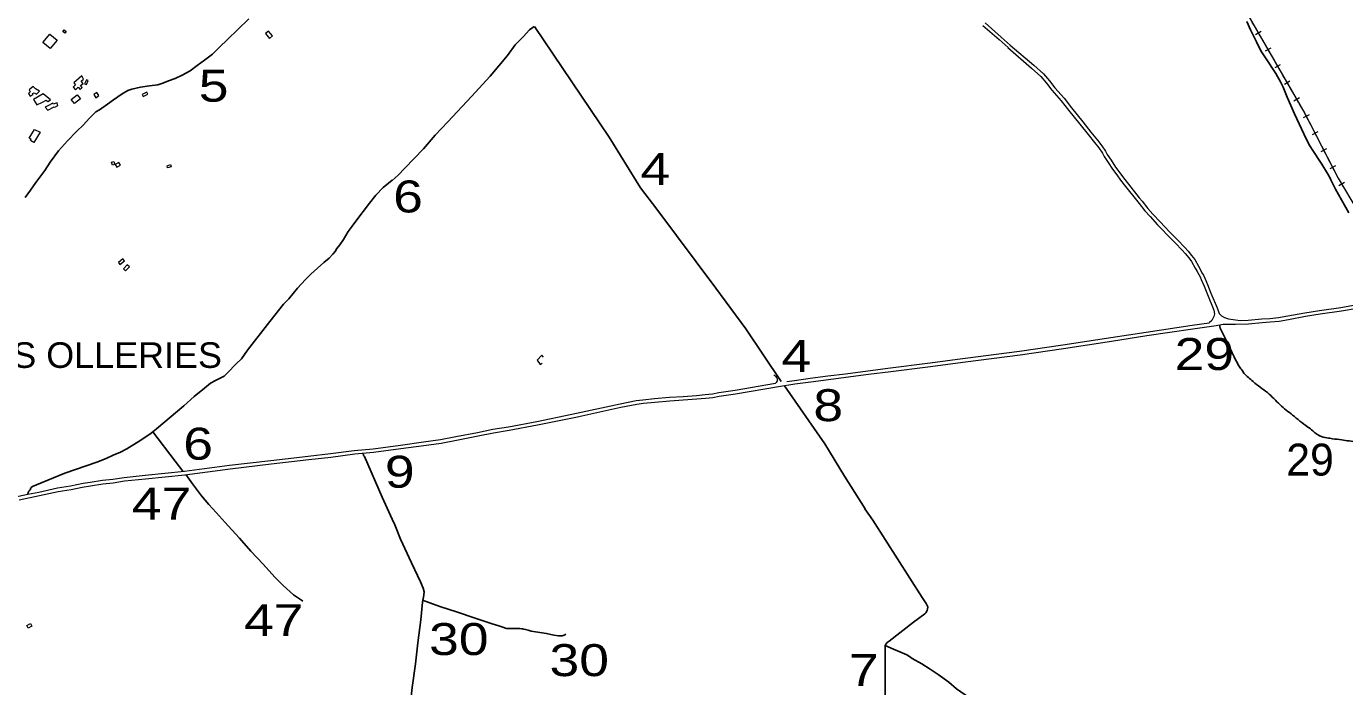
# Model space of a CAD drawing. Extents: x 476989 to 498418, y 4381813 to 4416555.
# Drawn here: x 485599 to 487660, y 4384627 to 4385659 of the extents above; entities that cross this region are included whole.
import ezdxf
from ezdxf.enums import TextEntityAlignment as Align

# ---------------------------------------------------------------- set-up
doc = ezdxf.new("R2010")
doc.units = 0
doc.header["$LTSCALE"] = 20
doc.linetypes.add('MEDIUM_DASHED', pattern=[4.5, 3, -1.5])
for name, color, linetype, lineweight in [('13', 7, 'Continuous', 13), ('34', 7, 'Continuous', 13), ('36', 7, 'Continuous', 13), ('47', 7, 'Continuous', 13), ('48', 7, 'MEDIUM_DASHED', 13), ('6', 7, 'Continuous', 25)]:
    doc.layers.add(name, color=color, linetype=linetype, lineweight=lineweight)
doc.layers.add('7', color=7, linetype='Continuous')

msp = doc.modelspace()

# ---------------------------------------------------------------- linework, layer by layer
at = {"layer": '34'}
for p, q in [((487515.47, 4385665.98), (487520.47, 4385657.32)), ((487529.79, 4385651.17), (487521.13, 4385646.17)), ((487522.96, 4385653), (487527.96, 4385644.34)), ((487530.46, 4385640.01), (487535.46, 4385631.35)), ((487537.96, 4385627.03), (487542.96, 4385618.36)), ((487544.79, 4385625.19), (487536.13, 4385620.2)), ((487545.45, 4385614.03), (487550.45, 4385605.37)), ((487559.78, 4385599.22), (487551.12, 4385594.22)), ((487552.95, 4385601.05), (487557.95, 4385592.39)), ((487560.45, 4385588.06), (487565.45, 4385579.4)), ((487574.77, 4385573.25), (487566.11, 4385568.25)), ((487567.94, 4385575.08), (487572.94, 4385566.42)), ((487575.44, 4385562.09), (487580.44, 4385553.43)), ((487589.76, 4385547.27), (487581.1, 4385542.27)), ((487582.93, 4385549.1), (487587.93, 4385540.44)), ((487590.43, 4385536.11), (487595.43, 4385527.45)), ((487604.67, 4385520.98), (487595.77, 4385516.4)), ((487604.8, 4385509.8), (487609.37, 4385500.91)), ((487618.39, 4385494.31), (487609.5, 4385489.74)), ((487611.66, 4385496.47), (487616.24, 4385487.58)), ((487618.53, 4385483.13), (487623.1, 4385474.24)), ((487632.12, 4385467.65), (487623.23, 4385463.07)), ((487625.39, 4385469.81), (487629.96, 4385460.92)), ((487632.25, 4385456.47), (487636.83, 4385447.58)), ((487639.11, 4385443.14), (487643.69, 4385434.25)), ((487645.85, 4385440.99), (487636.96, 4385436.41)), ((487660.04, 4385414.94), (487651.46, 4385409.81)), ((487653.19, 4385416.67), (487658.31, 4385408.09))]:
    msp.add_line(p, q, dxfattribs=at)
for points in [[(487280.6, 4386441.97), (487080, 4386339), (487267, 4386051), (487354, 4385933), (487441, 4385795), (487598, 4385523), (487650, 4385422), (487680.1, 4385371.64)], [(487597.92, 4385523.13), (487598, 4385523), (487602.51, 4385514.24)], [(487645.98, 4385429.81), (487650, 4385422), (487650.63, 4385420.95)]]:
    msp.add_lwpolyline(points, dxfattribs=at)
at = {"layer": '36'}
for points in [[(487094.87, 4385660.71), (487120.03, 4385638.46), (487134.03, 4385626.1)], [(487098.08, 4385664.55), (487123.34, 4385642.2), (487137.34, 4385629.84)], [(487137.34, 4385629.84), (487174.37, 4385598.25), (487189.49, 4385584.88), (487198.79, 4385573.94), (487207.09, 4385563.07), (487221.62, 4385546.65), (487233.12, 4385531.62), (487250.93, 4385509.8), (487263.67, 4385493.87), (487273.88, 4385481.46), (487280.75, 4385472.58), (487286.58, 4385464.01), (487289.2, 4385458.89), (487295.51, 4385449.72), (487302.21, 4385439.2), (487308.8, 4385430.25), (487314.57, 4385422.26), (487322.22, 4385412.29), (487339.33, 4385391.04), (487343.7, 4385385.7), (487352.58, 4385374.47), (487360.7, 4385365.72), (487372.3, 4385352.95), (487378.61, 4385346.17), (487387.71, 4385336.64), (487399.47, 4385324.69), (487410.47, 4385313.22), (487415.59, 4385307.71), (487421.16, 4385300.88), (487426.05, 4385294.47), (487431.8, 4385284.22), (487435.11, 4385278.47), (487437.31, 4385273.99), (487439.69, 4385270.26), (487441.61, 4385265.57), (487446.06, 4385255.26), (487451.29, 4385241.96), (487461.05, 4385218.86)], [(487133.89, 4385626.23), (487170.51, 4385593.8), (487185.28, 4385580.75), (487194.21, 4385570.25), (487202.54, 4385559.33), (487217.08, 4385542.91), (487228.5, 4385527.97), (487246.35, 4385506.1), (487259.1, 4385490.16), (487269.28, 4385477.79), (487275.98, 4385469.12), (487281.5, 4385461), (487284.13, 4385455.86), (487290.6, 4385446.47), (487297.35, 4385435.87), (487304.04, 4385426.78), (487309.85, 4385418.74), (487317.59, 4385408.66), (487334.76, 4385387.33), (487339.11, 4385382.01), (487348.1, 4385370.63), (487356.37, 4385361.74), (487367.97, 4385348.97), (487374.33, 4385342.13), (487383.49, 4385332.54), (487395.25, 4385320.59), (487406.19, 4385309.18), (487411.15, 4385303.84), (487416.54, 4385297.24), (487421.12, 4385291.23), (487426.69, 4385281.31), (487429.91, 4385275.71), (487432.17, 4385271.1), (487434.44, 4385267.53), (487436.19, 4385263.29), (487440.62, 4385253.02), (487445.84, 4385239.74), (487455.81, 4385215.58)], [(485587.94, 4384918.87), (485619.65, 4384925.47), (485648.99, 4384932.03), (485669.04, 4384935.03), (485686.15, 4384938.36), (485699.65, 4384940.84), (485718.69, 4384943.79), (485734.94, 4384945.58), (485752.53, 4384948.26), (485785.29, 4384951.54), (485846.98, 4384958.08), (485917.59, 4384967.28), (485981.92, 4384974.91), (486040.54, 4384981.65), (486075.35, 4384985.5), (486112.55, 4384990.45), (486141.85, 4384993.18), (486184.72, 4384998.94), (486220.81, 4385003.83), (486247.67, 4385007.48), (486271.61, 4385012.25), (486305.54, 4385018.75), (486329.76, 4385023.58), (486353.89, 4385027.57), (486398.31, 4385035.88), (486461.13, 4385048.69), (486462.73, 4385049.14), (486528.81, 4385063.65), (486553.7, 4385068.46), (486563.83, 4385069.82), (486581.63, 4385071.52), (486605.36, 4385073.58), (486626.31, 4385074.93), (486647.28, 4385076.51), (486661.18, 4385077.81), (486672.55, 4385078.92), (486682.57, 4385080.87), (486708.05, 4385084.63), (486775.37, 4385096.2), (486800.8, 4385100.04), (486825.52, 4385103.44), (486853.12, 4385107.17), (486880.63, 4385110.38), (486915.74, 4385115.13), (486950.76, 4385119.43), (487008.87, 4385126.93), (487067.66, 4385134.49), (487152.91, 4385145.5), (487220.82, 4385155.63), (487295.65, 4385167.08), (487350.85, 4385175.59), (487422.95, 4385186.43), (487459.43, 4385191.37), (487470.68, 4385193.32), (487489.65, 4385193.71), (487510.01, 4385193.94), (487531.2, 4385196.06), (487543.67, 4385196.93), (487557.74, 4385198.3), (487572.8, 4385201.01), (487598.91, 4385205.81), (487622.06, 4385209.39), (487655.21, 4385214.16), (487679.8, 4385218.38)], [(487455.81, 4385215.58), (487456.62, 4385209.72), (487455.81, 4385205.68), (487454.49, 4385202.09), (487452.5, 4385199.34), (487448.32, 4385195.53)], [(487461.05, 4385218.86), (487463.98, 4385210.29), (487467.68, 4385206.41), (487472.37, 4385203.71), (487478.72, 4385201.9), (487497.15, 4385199.42)], [(487497.15, 4385199.42), (487509.69, 4385199.56), (487530.73, 4385201.64), (487543.2, 4385202.51), (487556.97, 4385203.85), (487571.79, 4385206.52), (487597.97, 4385211.35), (487621.23, 4385214.93), (487654.34, 4385219.7), (487679.81, 4385224.07)], [(486788.13, 4385103.8), (486799.99, 4385105.59), (486824.76, 4385108.99), (486852.42, 4385112.73), (486879.93, 4385115.94), (486915.02, 4385120.69), (486950.06, 4385124.99), (487008.15, 4385132.49), (487066.94, 4385140.05), (487152.14, 4385151.05), (487219.98, 4385161.17), (487294.79, 4385172.63), (487350, 4385181.14), (487422.16, 4385191.98), (487448.32, 4385195.53)], [(485601.44, 4384927.38), (485618.46, 4384930.95), (485647.97, 4384937.54), (485668, 4384940.55), (485688.12, 4384944.59), (485698.86, 4384946.38), (485717.96, 4384949.34), (485734.21, 4384951.14), (485751.82, 4384953.82), (485784.71, 4384957.11), (485846.33, 4384963.64), (485916.89, 4384972.84), (485981.27, 4384980.47), (486039.91, 4384987.22), (486074.67, 4384991.06), (486111.92, 4384996.02), (486141.22, 4384998.75), (486183.97, 4385004.49), (486220.05, 4385009.38), (486246.73, 4385013.02), (486270.53, 4385017.75), (486304.46, 4385024.25), (486328.75, 4385029.09), (486352.92, 4385033.1), (486397.22, 4385041.38), (486452.17, 4385052.61), (486452.19, 4385052.58), (486527.68, 4385069.14), (486552.8, 4385074), (486563.2, 4385075.39), (486581.12, 4385077.1), (486604.95, 4385079.16), (486625.92, 4385080.52), (486646.81, 4385082.09), (486660.65, 4385083.38), (486671.74, 4385084.47), (486681.62, 4385086.4), (486707.17, 4385090.17), (486770.61, 4385101.07)], [(485422.69, 4384896.4), (485445.04, 4384898.28), (485457.06, 4384899.22), (485464.89, 4384900.34), (485474.69, 4384902.21), (485508.34, 4384907.79), (485538.44, 4384915.04), (485558.81, 4384919.82), (485586.93, 4384924.38), (485601.44, 4384927.38)]]:
    msp.add_lwpolyline(points, dxfattribs=at)
msp.add_spline([(486767.68, 4385114.39), (486772.5, 4385109.36), (486772.99, 4385106.58), (486772.97, 4385105.38), (486772.81, 4385104.41), (486772.42, 4385103.66), (486770.74, 4385101.28), (486770.61, 4385101.07)], degree=3, dxfattribs=at)
at = {"layer": '47'}
for points in [[(485635.68, 4385647.23), (485647.33, 4385637.86), (485636.56, 4385624.48), (485624.91, 4385633.85)], [(485658.29, 4385653.66), (485661.38, 4385650.92), (485659.34, 4385648.62), (485656.25, 4385651.36)], [(485973.2, 4385647.8), (485979.51, 4385640.27), (485984.18, 4385644.19), (485977.87, 4385651.72)], [(485619.69, 4385557.64), (485613.67, 4385561.55), (485609.59, 4385565.06), (485603.44, 4385559.82), (485605.27, 4385556.65), (485602.46, 4385554.21), (485604.95, 4385550.05), (485609.94, 4385552.83), (485608.92, 4385554.42), (485611.48, 4385555.06), (485615.13, 4385553.2)], [(485686, 4385582.05), (485673.31, 4385570.9), (485676.11, 4385567.69), (485672.26, 4385564.34), (485675.87, 4385560.17), (485680.34, 4385564.05), (485683.31, 4385560.61), (485686.6, 4385563.46), (485683.93, 4385566.52), (485687.71, 4385569.83), (485684.68, 4385573.28), (485688.41, 4385576.56)], [(485693.04, 4385575.65), (485690.28, 4385569.34), (485693, 4385568.15), (485695.76, 4385574.46)], [(485625.19, 4385553.51), (485610.05, 4385544.72), (485615.41, 4385536.24), (485624.62, 4385540.46), (485630.23, 4385543.98), (485632.89, 4385541.54), (485636.84, 4385544.49)], [(485683.68, 4385545.62), (485674.4, 4385538.3), (485669.11, 4385545), (485678.39, 4385552.32)], [(485709.41, 4385555.83), (485704.45, 4385552.39), (485707.72, 4385547.67), (485712.68, 4385551.11)], [(485787.53, 4385556.14), (485780.27, 4385552.57), (485781.8, 4385549.46), (485789.06, 4385553.03)], [(485647.5, 4385539.76), (485641.24, 4385537.45), (485640.36, 4385539.11), (485632.5, 4385534.95), (485628.57, 4385532.83), (485632.55, 4385528.34), (485642.83, 4385533.52), (485643.57, 4385532.76), (485648.26, 4385535.32)], [(485620.73, 4385493.69), (485610.59, 4385477.56), (485605.81, 4385480.55), (485606.79, 4385482.13), (485603.55, 4385484.13), (485612.08, 4385497.96)], [(485736, 4385447.7), (485737.37, 4385443.37), (485733.82, 4385442.25), (485732.45, 4385446.58)], [(485743.71, 4385446.46), (485738.03, 4385443.02), (485740.6, 4385438.78), (485746.28, 4385442.22)], [(485819.05, 4385441.33), (485824.55, 4385443.01), (485825.55, 4385439.73), (485820.05, 4385438.05)], [(485750.18, 4385295.54), (485742.99, 4385289.76), (485745.4, 4385286.76), (485752.59, 4385292.54)], [(485756.95, 4385286.22), (485750.76, 4385280.13), (485753.96, 4385276.88), (485760.15, 4385282.97)]]:
    msp.add_lwpolyline(points, close=True, dxfattribs=at)
at = {"layer": '48'}
msp.add_lwpolyline([(486407.83, 4385141.71), (486405.11, 4385144.87), (486397.87, 4385137.02), (486402.73, 4385130.49), (486405.67, 4385132.69)], dxfattribs=at)
msp.add_lwpolyline([(485599.77, 4384722.32), (485605.45, 4384725.41), (485607.85, 4384721), (485602.17, 4384717.91)], close=True, dxfattribs=at)
at = {"layer": '6'}
msp.add_line((486218.81, 4384761.9), (486218.38, 4384758.97), dxfattribs=at)
for points in [[(485597.52, 4385391.7), (485605.43, 4385403.19), (485614.06, 4385415.16), (485627.96, 4385433.84), (485636.16, 4385446.72), (485649.17, 4385464.38), (485663.28, 4385479.94), (485677.54, 4385494.69), (485688.56, 4385504.94), (485697.1, 4385515.25), (485707.8, 4385525.57), (485713.5, 4385528.66), (485725.91, 4385537.47), (485735.62, 4385544.46), (485748.75, 4385553.59), (485758, 4385558.72), (485764.17, 4385561.06), (485777.52, 4385563.88), (485791.81, 4385566), (485804.8, 4385567.91), (485812.68, 4385570.49), (485821.36, 4385573.88), (485831.97, 4385577.48), (485842.83, 4385582.78), (485855.2, 4385589.43), (485865.96, 4385597.89), (485877.72, 4385606.2), (485890.29, 4385615.9), (485901.17, 4385626.54), (485913.87, 4385638.89), (485929.7, 4385654.12), (485947.21, 4385671)], [(486171.07, 4385418.2), (486180.45, 4385426.71), (486190.85, 4385437.61), (486220.01, 4385467.74), (486238.45, 4385489.11), (486258.12, 4385510.06), (486294.91, 4385549.3), (486324.2, 4385581.38), (486338.08, 4385597.54), (486351.44, 4385613.56), (486363.48, 4385630.43), (486375.73, 4385642.67), (486386.01, 4385653.7), (486393.28, 4385659.16)], [(486779.18, 4385103.59), (486724.1, 4385186.32), (486677.34, 4385249.63), (486584.76, 4385373.47), (486559.43, 4385406.45), (486510.37, 4385486.01), (486393.48, 4385659.09)], [(487666.97, 4385367.8), (487655.53, 4385387.66), (487646.04, 4385404.85), (487638.87, 4385419.17), (487637.07, 4385422.61), (487633.76, 4385428.95), (487624.95, 4385443.57), (487619.44, 4385451.28), (487613.84, 4385460.27), (487610.6, 4385465.19), (487606.19, 4385472.22), (487600.82, 4385482.25), (487593.07, 4385498.8), (487581.97, 4385522.18), (487570.38, 4385548.55), (487564.1, 4385563.94), (487559.97, 4385572.22), (487552.83, 4385585.27), (487536.84, 4385609.75), (487529.21, 4385621.16), (487522.63, 4385634.9), (487513.12, 4385653.9), (487507.22, 4385666.93)], [(485802.83, 4385029.77), (485845.6, 4385065.72), (485861.7, 4385080.31), (485877.49, 4385093.53), (485887.3, 4385101.32), (485895.1, 4385105.6), (485908.18, 4385112.39), (485917.95, 4385121.44), (485922.84, 4385127.37), (485927.25, 4385131.59), (485935.63, 4385139.13), (485945.14, 4385152.95), (485979.77, 4385197.7), (486001.38, 4385224.55), (486009.54, 4385233.3), (486023.28, 4385249.97), (486035.47, 4385263.38), (486043.92, 4385271.58), (486054.18, 4385280.81), (486064.12, 4385289.68), (486072.49, 4385296.54), (486078.51, 4385302.83), (486081.98, 4385307.3), (486084.66, 4385311.91), (486089.01, 4385317.32), (486094.92, 4385325.79), (486102.37, 4385338.44), (486108.49, 4385346.61), (486117.22, 4385358.79), (486125.69, 4385369.55), (486135.5, 4385382.68), (486145.79, 4385395.36), (486157.22, 4385407.13), (486165.44, 4385414.11), (486171.07, 4385418.54)], [(487464.55, 4385192.26), (487465.84, 4385187.36), (487469.17, 4385179.71), (487475.3, 4385168.52), (487480.55, 4385157.4), (487484.26, 4385148.79), (487487.46, 4385142.3), (487489.64, 4385137.56), (487492.4, 4385133.28), (487494.08, 4385129.74), (487497.14, 4385125.28), (487498.2, 4385123.52), (487499.61, 4385121.88), (487500.43, 4385120.59), (487502.07, 4385118.13), (487502.9, 4385116.48)], [(486910.49, 4384904.75), (486878.56, 4384955.88), (486847.53, 4385006.24), (486784.74, 4385096.92)], [(485614.95, 4384942.15), (485659.47, 4384960.27), (485709.16, 4384977.93), (485723.74, 4384983.21), (485735, 4384988.39), (485746.12, 4384993.48), (485756.04, 4384998.3), (485778.17, 4385011.92), (485794.02, 4385023.23), (485802.57, 4385029.77)], [(485796.79, 4385025.24), (485831.62, 4384979.39), (485843.97, 4384963.6)], [(486127.68, 4384986.56), (486155.43, 4384923.07), (486171.13, 4384888.56), (486175.23, 4384879.77), (486183.98, 4384857.13), (486201.15, 4384820.46), (486215.43, 4384790.44), (486219.46, 4384780.68), (486220.96, 4384774.92), (486220.65, 4384770.31), (486219.83, 4384766.65), (486218.81, 4384761.72)], [(485848.5, 4384958.28), (485858.98, 4384943.82), (485873.22, 4384924.97), (485884.69, 4384911.41), (485895.78, 4384898.93), (485914.77, 4384877.86), (485932.13, 4384858.72), (485950.08, 4384838.41), (485969.52, 4384818.02), (485987.78, 4384798.02), (486000.62, 4384784.64), (486017.02, 4384770.37), (486029.23, 4384762), (486031.51, 4384760.15)], [(485614.95, 4384942.15), (485608.66, 4384939.57), (485606.61, 4384938.02), (485605.45, 4384935.86), (485604.91, 4384934.22), (485602.76, 4384932.09), (485601.81, 4384930.01), (485601.44, 4384927.75)], [(486941.95, 4384690.3), (486943.16, 4384693.25), (486945.3, 4384695.79), (486948.14, 4384697.69), (486986.16, 4384727.33), (487003.92, 4384740.66), (487005.68, 4384742.11), (487007.68, 4384745.56), (487008.31, 4384747.93), (487008.8, 4384751.24), (487006.22, 4384756.51), (486999.77, 4384765.9), (486922.59, 4384887.05), (486910.3, 4384904.56)], [(486218.76, 4384761.89), (486245.45, 4384751.89), (486273.45, 4384742.94), (486299.51, 4384734.09), (486327.45, 4384724.9), (486337.92, 4384721.6), (486344.05, 4384719.66), (486348.16, 4384717.88), (486349.85, 4384717.77), (486352.46, 4384717.35), (486354.83, 4384717.39), (486357.91, 4384717.42), (486366.72, 4384717.52), (486370.68, 4384717.4), (486373.62, 4384717.06), (486375.02, 4384716.9), (486376.21, 4384716.73), (486379.64, 4384716.24), (486383.69, 4384715.17), (486388.46, 4384713.49), (486412.51, 4384709.54), (486423.95, 4384707.2), (486431.5, 4384705.94), (486435.36, 4384705.89), (486437.1, 4384706.03), (486439.82, 4384706.92), (486442.71, 4384708.58)], [(486218.38, 4384758.97), (486215.66, 4384730.87), (486211.01, 4384695.06), (486207.54, 4384662.09), (486202.36, 4384625.46), (486200.14, 4384606.58), (486197.13, 4384584.8), (486195.49, 4384569.88), (486192.94, 4384553.94), (486192.12, 4384543.7), (486190.9, 4384532.35), (486188.75, 4384518.64), (486187.3, 4384506.44), (486183.04, 4384476.01), (486180.3, 4384454.17)], [(486945.56, 4384310.48), (486944.94, 4384355.68), (486944.63, 4384415.82), (486944.32, 4384439.71), (486942.16, 4384575.23), (486941.95, 4384690.43)], [(486942.08, 4384690.84), (486954.99, 4384685.27), (486964.75, 4384681.01), (486968.71, 4384679.29), (486972.07, 4384677.74), (486975.6, 4384676.25), (486980.04, 4384673.88), (486984.28, 4384670.81), (486999.05, 4384662.28), (487012.48, 4384653.89), (487024.7, 4384645.52), (487041.38, 4384633.38), (487053.31, 4384623.24), (487073.79, 4384609.31), (487096.07, 4384592.1), (487101.96, 4384587.52)]]:
    msp.add_lwpolyline(points, dxfattribs=at)
for points in [[(487503.02, 4385116.48), (487517.08, 4385103.65), (487539.5, 4385086.52), (487549.79, 4385077.07), (487559.41, 4385067.47), (487578.99, 4385051.21), (487590.49, 4385042.04), (487603.03, 4385032.63), (487610.45, 4385026.75), (487614.38, 4385023.32), (487616.24, 4385022.01), (487617.43, 4385021.32), (487619.51, 4385019.87), (487621.29, 4385018.79), (487632.76, 4385015.64), (487641.4, 4385014.37), (487655.73, 4385012.48), (487679.12, 4385009.11)], [(486127.68, 4384986.56), (486126.39, 4384988.54), (486125.72, 4384990.22), (486124.6, 4384991.34)]]:
    msp.add_spline(points, degree=3, dxfattribs=at)

# ---------------------------------------------------------------- texts
at = {"layer": '13', "width": 1.25}
for s, p in [('5', (485891.96, 4385541.41)), ('4', (486582.62, 4385411.14)), ('6', (486195.92, 4385368.17)), ('4', (486803.07, 4385118.78)), ('29', (487441.01, 4385121.82)), ('8', (486852.94, 4385041.77)), ('6', (485867.71, 4384981.53)), ('9', (486182.93, 4384937.71)), ('47', (485810.41, 4384887.83)), ('47', (485985.95, 4384705.57)), ('30', (486275.35, 4384676.03)), ('30', (486463.62, 4384643.08)), ('7', (486908.48, 4384627.5))]:
    msp.add_text(s, height=50, dxfattribs=at).set_placement(p, align=Align.CENTER)
at = {"layer": '13'}
msp.add_text('29', height=50, dxfattribs=at).set_placement((487569.08, 4384956.65))
at = {"layer": '7', "width": 1.05}
msp.add_text('SES OLLERIES', height=40, dxfattribs=at).set_placement((485703.59, 4385125.11), align=Align.CENTER)

doc.saveas('drawing.dxf')
